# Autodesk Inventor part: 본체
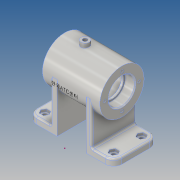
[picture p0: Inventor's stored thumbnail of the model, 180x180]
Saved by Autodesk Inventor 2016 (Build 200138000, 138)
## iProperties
Created: 2017-02
Part Number: 본체
Material: 알루미늄 6061
Document SubType Name: Modeling
Designer: Administrator
Density: 2.7 g/cm^3
Appearance: 알루미늄 - 평지
Author: Administrator
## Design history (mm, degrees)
sketch "스케치3"
  geometry: L1 (-52, 27)-(52, 27); L2 (52, 27)-(52, -27); L3 (52, -27)-(-52, -27); L4 (-52, -27)-(-52, 27); L5 (-52, 27)-(52, -27); L6 (52, 27)-(-52, -27); 1 further point
  constraints: 12 end point, 2 midpoint, 2 parallel, 1 horizontal, 1 perpendicular
  dimensions: "d4" = 104 distance of L2.end L3.end; "d5" = 54 distance of L1.end L2.end
extrude "돌출2" new body sketch "스케치3" distance "d6" = 8; taper "d7" = 0 deg
sketch "스케치4"
  geometry: L1 (35, 87)-(-35, 87); L2 (-48.062, 60)-(52.211, 60); L3 (-35, 87)-(-35, 60); L4 (35, 87)-(35, 60); L5 (52, 0)-(-52, 0) reference; L6 (-52, 8)-(52, 8) reference; 3 further points
  constraints: 8 end point, 2 horizontal, 2 midpoint, 2 perpendicular, 2 point on line, 1 parallel, 1 vertical alignment
  dimensions: "d8" = 70 distance of L1.start L1.end; "d9" = 54 diameter of L1.start L2; "d10" = 27 distance of L1.end L3.end (derived); "d11" = 60 distance from line of L5 L2.end
revolve "회전1" sketch "스케치4" stored, may be unused: angle "d12" = 90 deg
sketch "스케치6"
  geometry: L1 (-35, 33)-(-35, 87) reference; L2 (35, 33)-(35, 87) reference; L3 (-52, 0)-(52, 0) reference; L4 (-52, 0)-(-52, 8) reference; L5 (52, 8)-(-52, 8) reference; L6 (52, 0)-(52, 8) reference; L7 (-35, 87)-(35, 87) reference; L8 (41.911, 60)-(-41.911, 60); L9 (35, 33)-(35, 87) reference; L10 (35, 76)-(23, 76); L11 (23, 76)-(23, 74); L12 (23, 74)-(20, 74); L13 (20, 74)-(20, 82); L14 (20, 82)-(-20, 82); L15 (-20, 82)-(-20, 74); L16 (-20, 74)-(-23, 74); L17 (-23, 74)-(-23, 76); L18 (-23, 76)-(-35, 76); L19 (35, 76)-(35, 60); L20 (-35, 76)-(-35, 60); L21 (-35, 33)-(-35, 87) reference; L22 (35, 60)-(-35, 60); 6 further points
  constraints: 26 end point, 8 perpendicular, 5 midpoint, 3 point on line, 3 vertical alignment, 1 collinear, 1 horizontal
  dimensions: "d13" = 32 diameter of L10.start L8; "d14" = 28 diameter of L11.end L8; "d15" = 44 diameter of L13.end L8; "d16" = 28 diameter of L15.end L8 (derived); "d17" = 32 diameter of L17.end L8; "d18" = 12 distance between parallel lines of L11 L2; "d19" = 3 distance between parallel lines of L13 L11; "d20" = 3 distance between parallel lines of L17 L15; "d21" = 12 distance between parallel lines of L20 L17; "d24" = 60 distance between parallel lines of L3 L22 (derived)
revolve "회전2" sketch "스케치6" stored, may be unused: angle "d25" = 90 deg
sketch "스케치7" dims "d27" = 42
  geometry: L1 (-27, -60)-(-27, -52) reference; L2 (-27, -52)-(27, -52) reference; L3 (27, -52)-(27, -60) reference; L4 (27, -60)-(-27, -60) reference; C1 r 14 at (0, 0) reference; C2 r 16 at (0, 0) reference; C3 r 27 at (0, 0) reference; 3 further points
  constraints: 1 coincident, 1 vertical alignment, 2 other
hole "구멍1" sketch "스케치7" at (0, 21) diameter "d28" = 3.242; stored, may be unused: countersink angle "d32" = 90 deg, drill point angle "d34" = 118 deg; dims "d29" = 8, "d30" = 8, "d31" = 2, "d33" = 10
sketch "스케치8" dims "d38" = 42
  geometry: C1 r 27 at (0, 0) reference; 3 further points
  constraints: 1 coincident, 1 vertical alignment, 2 other
hole "구멍2" sketch "스케치8" at (0, 21) diameter "d39" = 3.242; stored, may be unused: countersink angle "d43" = 90 deg, drill point angle "d45" = 118 deg; dims "d40" = 8, "d41" = 8, "d42" = 2, "d44" = 10
sketch "스케치10"
  geometry: L1 (-63.632, 0)-(61.435, 0); L2 (0, -27)-(0, 27); L3 (-17, -27)-(-17, 27); L4 (17, -27)-(17, 27); L5 (-17, -27)-(17, -27); L6 (17, 27)-(-17, 27); 1 further point
  constraints: 12 end point
  dimensions: "d49" = 17 distance between parallel lines of L2 L3; "d50" = 17 distance between parallel lines of L2 L4
extrude "돌출3" cut sketch "스케치10" stored distance "d52" = 8; taper "d53" = 0 deg
sketch "스케치11"
  geometry: L1 (-17, -27)-(-17, 27) reference; L2 (-25, -27)-(-25, 27); L3 (-25, -27)-(-17, -27); L4 (-17, 27)-(-25, 27); 1 further point
  constraints: 6 end point
  dimensions: "d54" = 8 distance between parallel lines of L1 L2
extrude "돌출4" join sketch "스케치11" stored distance "d55" = 8; taper "d56" = 0 deg
fillet "모깎기1" dims "d57" = 10
sketch "스케치12" dims "d58" = 9
  geometry: L1 (44.598, 21.5)-(47.196, 17); L2 (47.196, 17)-(44.598, 12.5); L3 (44.598, 12.5)-(39.402, 12.5); L4 (39.402, 12.5)-(36.804, 17); L5 (36.804, 17)-(39.402, 21.5); L6 (39.402, 21.5)-(44.598, 21.5); L7 (44.598, -12.5)-(47.196, -17); L8 (47.196, -17)-(44.598, -21.5); L9 (44.598, -21.5)-(39.402, -21.5); L10 (39.402, -21.5)-(36.804, -17); L11 (36.804, -17)-(39.402, -12.5); L12 (39.402, -12.5)-(44.598, -12.5); L13 (-39.402, -12.5)-(-36.804, -17); L14 (-36.804, -17)-(-39.402, -21.5); L15 (-39.402, -21.5)-(-44.598, -21.5); L16 (-44.598, -21.5)-(-47.196, -17); L17 (-47.196, -17)-(-44.598, -12.5); L18 (-44.598, -12.5)-(-39.402, -12.5); L19 (-39.402, 21.5)-(-36.804, 17); L20 (-36.804, 17)-(-39.402, 12.5); L21 (-39.402, 12.5)-(-44.598, 12.5); L22 (-44.598, 12.5)-(-47.196, 17); L23 (-47.196, 17)-(-44.598, 21.5); L24 (-44.598, 21.5)-(-39.402, 21.5); C1 r 2.5 at (42, -17); C2 r 2.5 at (42, 17); C3 r 2.5 at (-42, 17); C4 r 2.5 at (-42, -17); A1 r 10 centre (-42, 17) between (-42, 27) and (-52, 17) reference; A2 r 10 centre (-42, -17) between (-52, -17) and (-42, -27) reference; A3 r 10 centre (42, -17) between (42, -27) and (52, -17) reference; A4 r 10 centre (42, 17) between (52, 17) and (42, 27) reference; 13 further points
  constraints: 48 end point, 12 coincident, 4 centre point, 4 midpoint, 4 vertical alignment, 3 equal radius, 2 point on line, 60 other
  dimensions: "d59" = 5 diameter of C1
extrude "돌출5" cut sketch "스케치12" distance "d60" = 3; taper "d61" = 0 deg
extrude "돌출6" cut sketch "스케치12" stored distance "d62" = 0; taper "d63" = 0 deg
fillet "모깎기2" dims "d64" = 2
fillet "모깎기3" dims "d65" = 2
node "작업 평면2"
sketch "스케치16"
  geometry: L1 (35, 27)-(35, -27) reference; L2 (35, 0)-(10, 0); C1 r 5 at (10, 0); 1 further point
  constraints: 2 end point, 1 centre point, 1 coincident, 1 horizontal, 1 midpoint
  dimensions: "d74" = 25 distance of L2.start L2.end; "d75" = 10 diameter of C1
extrude "돌출7" join sketch "스케치16" stored distance "d76" = 3; taper "d77" = 0 deg
sketch "스케치17"
  geometry: C1 r 5 at (0, 0) reference; 2 further points
  constraints: 1 coincident
hole "구멍3" sketch "스케치17" at (0, 0) diameter "d78" = 5.188; stored, may be unused: countersink angle "d82" = 90 deg, drill point angle "d84" = 0 deg; dims "d79" = 12, "d80" = 11, "d81" = 2.6, "d83" = 16
sketch "스케치23"
  geometry: 1 further point
sketch "스케치24"
  geometry: 1 further point
node "작업 평면4"
sketch "스케치25"
  geometry: C1 r 6 at (0, -14.704); 2 further points
  constraints: 1 centre point, 1 coincident
  dimensions: "d88" = 12 diameter of C1
extrude "돌출8" join sketch "스케치25" stored distance "d89" = 5; taper "d90" = 0 deg
sketch "스케치26"
  geometry: C1 r 6 at (0, 0) reference; 2 further points
  constraints: 1 coincident
hole "구멍4" sketch "스케치26" at (0, 0) diameter "d91" = 5.188; stored, may be unused: countersink angle "d95" = 90 deg, drill point angle "d97" = 0 deg; dims "d92" = 12, "d93" = 11, "d94" = 2.6, "d96" = 16
chamfer "모따기1" distance "d98" = 1; stored, may be unused: second distance "d99" = 2, angle "d100" = 45 deg
fillet "모깎기4" dims "d101" = 2
fillet "모깎기5" dims "d102" = 0.3
node "작업 평면5"
sketch "스케치28"
  geometry: 2 further points
  constraints: 1 vertical alignment, 1 other
node "솔리드2"
pattern_circular "원형 패턴1" dims angle "d36" = 360 deg
pattern_circular "원형 패턴2" dims angle "d47" = 360 deg
mirror "대칭1"
node "투영된 루프1"
node "투영된 루프2"
node "절단 모서리 투영2"
other parameters: "d73" = 92, "d103" = 35
